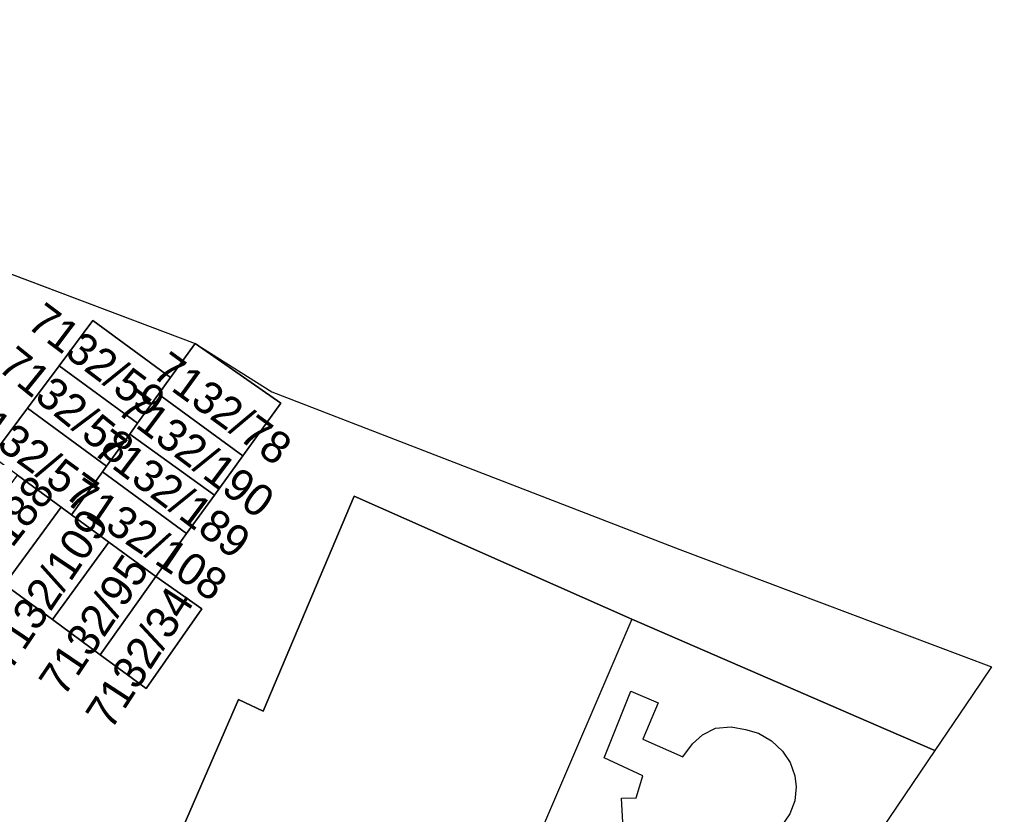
# Model space of a CAD drawing. Extents: x -266199 to -261993, y -1239047 to -1235108.
# Drawn here: x -263424.4 to -263363.8, y -1236181.4 to -1236131.9 of the extents above; entities that cross this region are included whole.
import ezdxf

# ---------------------------------------------------------------- set-up
doc = ezdxf.new("R2010")
doc.units = 0
for name, color, linetype in [('body_kn', 7, 'Continuous'), ('kladpar_druhypozemkov', 7, 'Continuous'), ('kladpar_hranice', 7, 'Continuous'), ('kladpar_parcelnecisla', 7, 'Continuous'), ('kladpar_plochy', 7, 'Continuous'), ('zappar_hrandruhpozemk', 7, 'Continuous'), ('zuob_linie', 7, 'Continuous'), ('zuob_plochy', 7, 'Continuous')]:
    doc.layers.add(name, color=color, linetype=linetype)

msp = doc.modelspace()

# ---------------------------------------------------------------- linework, layer by layer
at = {"layer": 'body_kn'}
for p, q in [((-263419.83, -1236150.62), (-263419.83, -1236150.62)), ((-263419.83, -1236150.62), (-263419.83, -1236150.62)), ((-263413.44, -1236152.05), (-263413.44, -1236152.05)), ((-263413.44, -1236152.05), (-263413.44, -1236152.05)), ((-263421.93, -1236153.44), (-263421.93, -1236153.44)), ((-263414.98, -1236154.17), (-263414.98, -1236154.17)), ((-263415.73, -1236155.21), (-263415.73, -1236155.21)), ((-263408.66, -1236155.08), (-263408.66, -1236155.08)), ((-263423.9, -1236156.08), (-263423.9, -1236156.08)), ((-263408.11, -1236155.77), (-263408.11, -1236155.77)), ((-263417.04, -1236157.03), (-263417.04, -1236157.03)), ((-263417.04, -1236157.03), (-263417.04, -1236157.03)), ((-263417.53, -1236157.7), (-263417.53, -1236157.7)), ((-263410.48, -1236159.06), (-263410.48, -1236159.06)), ((-263410.48, -1236159.06), (-263410.48, -1236159.06)), ((-263418.97, -1236159.7), (-263418.97, -1236159.7)), ((-263419.23, -1236160.06), (-263419.23, -1236160.06)), ((-263419.23, -1236160.06), (-263419.23, -1236160.06)), ((-263412.24, -1236161.51), (-263412.24, -1236161.51)), ((-263412.24, -1236161.51), (-263412.24, -1236161.51)), ((-263403.53, -1236161.57), (-263403.53, -1236161.57)), ((-263403.53, -1236161.57), (-263403.53, -1236161.57)), ((-263421.81, -1236162.26), (-263421.81, -1236162.26)), ((-263421.81, -1236162.26), (-263421.81, -1236162.26)), ((-263421.16, -1236162.73), (-263421.16, -1236162.73)), ((-263413.98, -1236163.91), (-263413.98, -1236163.91)), ((-263413.98, -1236163.91), (-263413.98, -1236163.91)), ((-263418.83, -1236164.44), (-263418.83, -1236164.44)), ((-263418.83, -1236164.44), (-263418.83, -1236164.44)), ((-263383.22, -1236164.89), (-263383.22, -1236164.89)), ((-263415.9, -1236166.59), (-263415.9, -1236166.59)), ((-263415.9, -1236166.59), (-263415.9, -1236166.59)), ((-263413.04, -1236168.6), (-263413.04, -1236168.6)), ((-263422.35, -1236169.26), (-263422.35, -1236169.26)), ((-263386.23, -1236169.24), (-263386.23, -1236169.24)), ((-263386.23, -1236169.24), (-263386.23, -1236169.24)), ((-263419.37, -1236171.46), (-263419.37, -1236171.46)), ((-263363.79, -1236172.22), (-263363.79, -1236172.22)), ((-263416.51, -1236173.56), (-263416.51, -1236173.56)), ((-263386.29, -1236173.72), (-263386.29, -1236173.72)), ((-263410.74, -1236174.24), (-263410.74, -1236174.24)), ((-263365, -1236174), (-263365, -1236174)), ((-263409.21, -1236174.98), (-263409.21, -1236174.98)), ((-263384.57, -1236174.46), (-263384.57, -1236174.46)), ((-263381, -1236176.04), (-263381, -1236176.04)), ((-263380.03, -1236175.96), (-263380.03, -1236175.96)), ((-263379.14, -1236176.12), (-263379.14, -1236176.12)), ((-263370.37, -1236176.11), (-263370.37, -1236176.11)), ((-263385.53, -1236176.73), (-263385.53, -1236176.73)), ((-263381.82, -1236176.45), (-263381.82, -1236176.45)), ((-263378.33, -1236176.35), (-263378.33, -1236176.35)), ((-263377.52, -1236176.83), (-263377.52, -1236176.83)), ((-263382.44, -1236177.01), (-263382.44, -1236177.01)), ((-263376.83, -1236177.46), (-263376.83, -1236177.46)), ((-263367.32, -1236177.43), (-263367.32, -1236177.43)), ((-263387.95, -1236177.88), (-263387.95, -1236177.88)), ((-263383.03, -1236177.82), (-263383.03, -1236177.82)), ((-263376.34, -1236178.17), (-263376.34, -1236178.17)), ((-263385.54, -1236179), (-263385.54, -1236179)), ((-263376.06, -1236179), (-263376.06, -1236179)), ((-263375.97, -1236179.69), (-263375.97, -1236179.69)), ((-263386.87, -1236180.4), (-263386.87, -1236180.4)), ((-263385.96, -1236180.38), (-263385.96, -1236180.38)), ((-263376.05, -1236180.57), (-263376.05, -1236180.57)), ((-263376.36, -1236181.38), (-263376.36, -1236181.38))]:
    msp.add_line(p, q, dxfattribs=at)
at = {"layer": 'kladpar_druhypozemkov'}
for p, q in [((-263418.13, -1236153.16), (-263418.13, -1236153.16)), ((-263411.82, -1236154.43), (-263411.82, -1236154.43)), ((-263419.96, -1236156.18), (-263419.96, -1236156.18)), ((-263413.82, -1236157.72), (-263413.82, -1236157.72)), ((-263422.29, -1236158.72), (-263422.29, -1236158.72)), ((-263415.28, -1236160.24), (-263415.28, -1236160.24)), ((-263417.25, -1236162.71), (-263417.25, -1236162.71)), ((-263422.52, -1236165.48), (-263422.52, -1236165.48)), ((-263419.46, -1236167.5), (-263419.46, -1236167.5)), ((-263416.71, -1236169.58), (-263416.71, -1236169.58))]:
    msp.add_line(p, q, dxfattribs=at)
at = {"layer": 'kladpar_hranice'}
for points in [[(-263442.82, -1236140.99), (-263413.44, -1236152.05), (-263414.98, -1236154.17), (-263419.83, -1236150.62), (-263421.93, -1236153.44), (-263423.9, -1236156.08), (-263426.14, -1236159.08)], [(-263419.83, -1236150.62), (-263414.98, -1236154.17), (-263415.73, -1236155.21), (-263417.04, -1236157.03), (-263421.93, -1236153.44), (-263419.83, -1236150.62)], [(-263425.33, -1236167.07), (-263422.35, -1236169.26), (-263419.37, -1236171.46), (-263416.51, -1236173.56), (-263413.04, -1236168.6), (-263415.9, -1236166.59), (-263413.98, -1236163.91), (-263412.24, -1236161.51), (-263410.48, -1236159.06), (-263408.11, -1236155.77), (-263413.44, -1236152.05), (-263408.66, -1236155.08), (-263383.22, -1236164.89), (-263363.79, -1236172.22), (-263365, -1236174), (-263367.32, -1236177.43), (-263370.37, -1236176.11), (-263386.23, -1236169.24), (-263403.53, -1236161.57), (-263409.21, -1236174.98), (-263410.74, -1236174.24), (-263414.19, -1236182.19)], [(-263413.44, -1236152.05), (-263408.11, -1236155.77), (-263410.48, -1236159.06), (-263415.73, -1236155.21), (-263414.98, -1236154.17), (-263413.44, -1236152.05)], [(-263417.04, -1236157.03), (-263417.53, -1236157.7), (-263418.97, -1236159.7), (-263423.9, -1236156.08), (-263421.93, -1236153.44), (-263417.04, -1236157.03)], [(-263410.48, -1236159.06), (-263412.24, -1236161.51), (-263417.53, -1236157.7), (-263417.04, -1236157.03), (-263415.73, -1236155.21), (-263410.48, -1236159.06)], [(-263419.23, -1236160.06), (-263421.16, -1236162.73), (-263421.81, -1236162.26), (-263424.53, -1236160.26), (-263426.14, -1236159.08), (-263423.9, -1236156.08), (-263418.97, -1236159.7), (-263419.23, -1236160.06)], [(-263412.24, -1236161.51), (-263413.98, -1236163.91), (-263419.23, -1236160.06), (-263418.97, -1236159.7), (-263417.53, -1236157.7), (-263412.24, -1236161.51)], [(-263424.53, -1236160.26), (-263421.81, -1236162.26), (-263425.33, -1236167.07), (-263428.06, -1236165.06), (-263424.53, -1236160.26)], [(-263413.98, -1236163.91), (-263415.9, -1236166.59), (-263418.83, -1236164.44), (-263421.16, -1236162.73), (-263419.23, -1236160.06), (-263413.98, -1236163.91)], [(-263414.19, -1236182.19), (-263410.74, -1236174.24), (-263409.21, -1236174.98), (-263403.53, -1236161.57)], [(-263403.53, -1236161.57), (-263386.23, -1236169.24), (-263370.37, -1236176.11), (-263367.32, -1236177.43), (-263373.94, -1236187.19)], [(-263421.81, -1236162.26), (-263421.16, -1236162.73), (-263418.83, -1236164.44), (-263422.35, -1236169.26), (-263425.33, -1236167.07), (-263421.81, -1236162.26)], [(-263418.83, -1236164.44), (-263415.9, -1236166.59), (-263419.37, -1236171.46), (-263422.35, -1236169.26), (-263418.83, -1236164.44)], [(-263415.9, -1236166.59), (-263413.04, -1236168.6), (-263416.51, -1236173.56), (-263419.37, -1236171.46), (-263415.9, -1236166.59)]]:
    msp.add_lwpolyline(points, dxfattribs=at)
at = {"layer": 'kladpar_plochy'}
for p, q in [((-263442.82, -1236140.99), (-263413.44, -1236152.05)), ((-263419.83, -1236150.62), (-263421.93, -1236153.44)), ((-263414.98, -1236154.17), (-263419.83, -1236150.62)), ((-263413.44, -1236152.05), (-263414.98, -1236154.17)), ((-263408.11, -1236155.77), (-263413.44, -1236152.05)), ((-263413.44, -1236152.05), (-263408.66, -1236155.08)), ((-263421.93, -1236153.44), (-263423.9, -1236156.08)), ((-263408.66, -1236155.08), (-263383.22, -1236164.89)), ((-263423.9, -1236156.08), (-263426.14, -1236159.08)), ((-263410.48, -1236159.06), (-263408.11, -1236155.77)), ((-263412.24, -1236161.51), (-263410.48, -1236159.06)), ((-263413.98, -1236163.91), (-263412.24, -1236161.51)), ((-263403.53, -1236161.57), (-263409.21, -1236174.98)), ((-263386.23, -1236169.24), (-263403.53, -1236161.57)), ((-263415.9, -1236166.59), (-263413.98, -1236163.91)), ((-263383.22, -1236164.89), (-263363.79, -1236172.22)), ((-263425.33, -1236167.07), (-263422.35, -1236169.26)), ((-263413.04, -1236168.6), (-263415.9, -1236166.59)), ((-263416.51, -1236173.56), (-263413.04, -1236168.6)), ((-263422.35, -1236169.26), (-263419.37, -1236171.46)), ((-263370.37, -1236176.11), (-263386.23, -1236169.24)), ((-263419.37, -1236171.46), (-263416.51, -1236173.56)), ((-263363.79, -1236172.22), (-263365, -1236174)), ((-263410.74, -1236174.24), (-263414.19, -1236182.19)), ((-263409.21, -1236174.98), (-263410.74, -1236174.24)), ((-263365, -1236174), (-263367.32, -1236177.43)), ((-263367.32, -1236177.43), (-263370.37, -1236176.11))]:
    msp.add_line(p, q, dxfattribs=at)
for points in [[(-263419.83, -1236150.62), (-263414.98, -1236154.17), (-263415.73, -1236155.21), (-263417.04, -1236157.03), (-263421.93, -1236153.44)], [(-263413.44, -1236152.05), (-263408.11, -1236155.77), (-263410.48, -1236159.06), (-263415.73, -1236155.21), (-263414.98, -1236154.17)], [(-263417.04, -1236157.03), (-263417.53, -1236157.7), (-263418.97, -1236159.7), (-263423.9, -1236156.08), (-263421.93, -1236153.44)], [(-263410.48, -1236159.06), (-263412.24, -1236161.51), (-263417.53, -1236157.7), (-263417.04, -1236157.03), (-263415.73, -1236155.21)], [(-263419.23, -1236160.06), (-263421.16, -1236162.73), (-263421.81, -1236162.26), (-263424.53, -1236160.26), (-263426.14, -1236159.08), (-263423.9, -1236156.08), (-263418.97, -1236159.7)], [(-263412.24, -1236161.51), (-263413.98, -1236163.91), (-263419.23, -1236160.06), (-263418.97, -1236159.7), (-263417.53, -1236157.7)], [(-263424.53, -1236160.26), (-263421.81, -1236162.26), (-263425.33, -1236167.07), (-263428.06, -1236165.06)], [(-263413.98, -1236163.91), (-263415.9, -1236166.59), (-263418.83, -1236164.44), (-263421.16, -1236162.73), (-263419.23, -1236160.06)], [(-263421.81, -1236162.26), (-263421.16, -1236162.73), (-263418.83, -1236164.44), (-263422.35, -1236169.26), (-263425.33, -1236167.07)], [(-263418.83, -1236164.44), (-263415.9, -1236166.59), (-263419.37, -1236171.46), (-263422.35, -1236169.26)], [(-263415.9, -1236166.59), (-263413.04, -1236168.6), (-263416.51, -1236173.56), (-263419.37, -1236171.46)]]:
    msp.add_lwpolyline(points, close=True, dxfattribs=at)
msp.add_lwpolyline([(-263414.19, -1236182.19), (-263410.74, -1236174.24), (-263409.21, -1236174.98), (-263403.53, -1236161.57), (-263386.23, -1236169.24), (-263370.37, -1236176.11), (-263367.32, -1236177.43), (-263373.94, -1236187.19)], dxfattribs=at)
at = {"layer": 'zappar_hrandruhpozemk'}
for p, q in [((-263386.23, -1236169.24), (-263401.54, -1236205.01)), ((-263387.95, -1236177.88), (-263386.29, -1236173.72))]:
    msp.add_line(p, q, dxfattribs=at)
for points in [[(-263386.29, -1236173.72), (-263384.57, -1236174.46), (-263385.53, -1236176.73), (-263383.03, -1236177.82), (-263382.44, -1236177.01), (-263381.82, -1236176.45), (-263381, -1236176.04), (-263380.03, -1236175.96), (-263379.14, -1236176.12), (-263378.33, -1236176.35), (-263377.52, -1236176.83), (-263376.83, -1236177.46), (-263376.34, -1236178.17), (-263376.06, -1236179), (-263375.97, -1236179.69), (-263376.05, -1236180.57), (-263376.36, -1236181.38), (-263376.87, -1236182.1)], [(-263392.73, -1236191.19), (-263390.81, -1236191.11), (-263390.93, -1236189.52), (-263389.94, -1236189.49), (-263390.11, -1236187.73), (-263389.16, -1236187.68), (-263389.29, -1236185.93), (-263388.34, -1236185.84), (-263388.5, -1236184.08), (-263387.55, -1236184.04), (-263387.67, -1236182.21), (-263386.77, -1236182.28), (-263386.87, -1236180.4), (-263385.96, -1236180.38), (-263385.54, -1236179), (-263387.95, -1236177.88)]]:
    msp.add_lwpolyline(points, dxfattribs=at)
at = {"layer": 'zuob_linie'}
msp.add_lwpolyline([(-263471.6, -1236129.07), (-263458.94, -1236134.31), (-263442.82, -1236140.99), (-263413.44, -1236152.05), (-263408.66, -1236155.08), (-263383.22, -1236164.89), (-263363.79, -1236172.22), (-263365, -1236174), (-263367.32, -1236177.43), (-263373.94, -1236187.19), (-263375.19, -1236189.03), (-263379.25, -1236197.36), (-263383.14, -1236205.34), (-263384.3, -1236207.75), (-263387.78, -1236215), (-263388.23, -1236216.27), (-263391.58, -1236225.78), (-263397.59, -1236242.84), (-263397.93, -1236262.41), (-263393.42, -1236263.62)], dxfattribs=at)
at = {"layer": 'zuob_plochy'}
msp.add_lwpolyline([(-263471.6, -1236129.07), (-263458.94, -1236134.31), (-263442.82, -1236140.99), (-263413.44, -1236152.05), (-263408.66, -1236155.08), (-263383.22, -1236164.89), (-263363.79, -1236172.22), (-263365, -1236174), (-263367.32, -1236177.43), (-263373.94, -1236187.19), (-263375.19, -1236189.03), (-263379.25, -1236197.36), (-263383.14, -1236205.34), (-263384.3, -1236207.75), (-263387.78, -1236215), (-263388.23, -1236216.27), (-263391.58, -1236225.78), (-263397.59, -1236242.84), (-263397.93, -1236262.41), (-263393.42, -1236263.62)], dxfattribs=at)

# ---------------------------------------------------------------- texts
at = {"layer": 'kladpar_parcelnecisla'}
for s, rotation, p in [('7132/59', 323, (-263424.033, -1236150.99)), ('7132/58', 321, (-263425.852, -1236153.643)), ('7132/78', 324, (-263416.232, -1236154.063)), ('7132/190', 323, (-263418.435, -1236156.332)), ('7132/57', 324, (-263428.297, -1236156.774)), ('7132/189', 323, (-263419.925, -1236158.862)), ('7132/188', 52, (-263428.984, -1236170.125)), ('7132/108', 326, (-263421.619, -1236161.968)), ('7132/109', 56, (-263424.979, -1236172.529)), ('7132/95', 56, (-263421.648, -1236174.156)), ('7132/34', 57, (-263418.704, -1236176.224))]:
    msp.add_text(s, height=2, rotation=rotation, dxfattribs=at).set_placement(p)

doc.saveas('drawing.dxf')
